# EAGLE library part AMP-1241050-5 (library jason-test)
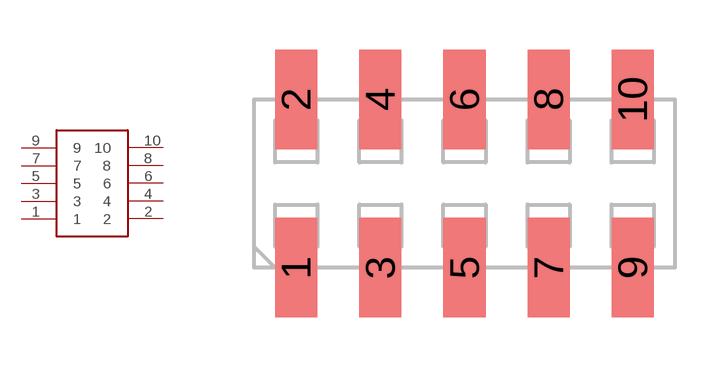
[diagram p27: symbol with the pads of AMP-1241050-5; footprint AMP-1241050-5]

Designator prefix -

## AMP-1241050-5  [AMP-1241050-5]
1  1
2  2
3  3
4  4
5  5
6  6
7  7
8  8
9  9
10  10

## Footprint AMP-1241050-5 (pad centres in mm)
smd 1.27 x 3: 1 -5.08,-2.54; 2 -5.08,2.54; 3 -2.54,-2.54; 4 -2.54,2.54; 5 0,-2.54; 6 0,2.54; 7 2.54,-2.54; 8 2.54,2.54; 9 5.08,-2.54; 10 5.08,2.54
